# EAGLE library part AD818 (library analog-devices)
Low Cost, Low Power Video Op Amp Source: http://www.analog.com/static/imported-files/data_sheets/AD818.pdf
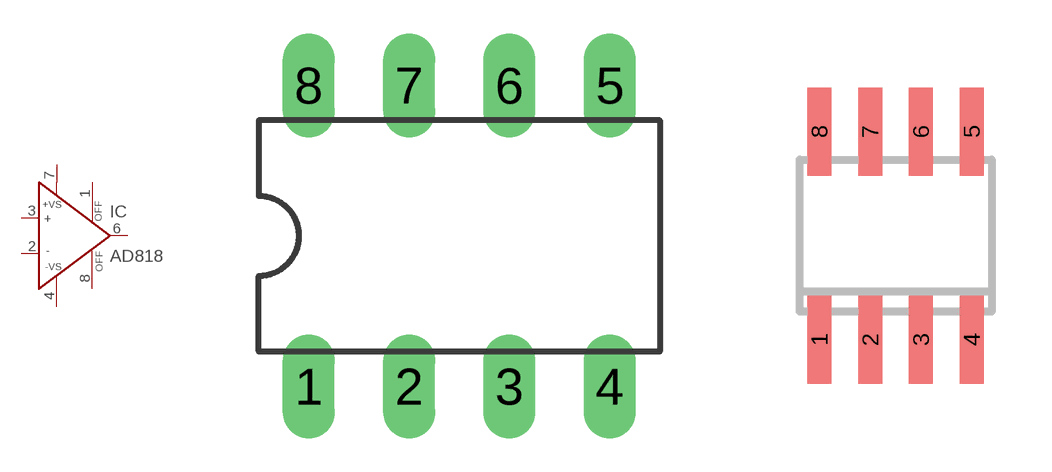
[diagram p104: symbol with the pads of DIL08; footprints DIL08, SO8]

Designator prefix IC

## AD818N (OC_FARNELL: 9605630; OC_NEWARK: unknown)  [DIL08]
1  OFF  pas
2  IN-  in
3  IN+  in
4  -VS  in
6  OUT  out
7  +VS  in
8  OFF  pas

## AD818R (MF: ALTERA CORPORATION; MPN: AD818ARZ; OC_FARNELL: unknown; OC_NEWARK: 82H2988)  [SO8]
Pads as for DIL08

## Footprint DIL08 (pad centres in mm)
Dual In Line Package
drill 0.813 long: 1 -3.81,-3.81; 2 -1.27,-3.81; 3 1.27,-3.81; 4 3.81,-3.81; 5 3.81,3.81; 6 1.27,3.81; 7 -1.27,3.81; 8 -3.81,3.81

## Footprint SO8 (pad centres in mm)
8-Lead Small Outline IC (SO-8) Source: http://www.analog.com/UploadedFiles/Data_Sheets/703465986AD8611_2_0.pdf
smd 0.6 x 2.2: 1 -1.905,-2.6; 2 -0.635,-2.6; 3 0.635,-2.6; 4 1.905,-2.6; 5 1.905,2.6; 6 0.635,2.6; 7 -0.635,2.6; 8 -1.905,2.6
